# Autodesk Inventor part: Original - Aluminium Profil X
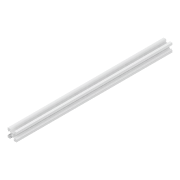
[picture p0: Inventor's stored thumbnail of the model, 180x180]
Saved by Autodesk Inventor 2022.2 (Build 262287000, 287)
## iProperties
Created: 2024-09
Part Number: Original - Aluminium Profil X
Material: Alluminio 6061
Document SubType Name: Modeling
Designer: 18907419
Density: 2.7 g/cm^3
Appearance: Alluminio - Piatto
Author: 18907419
Revision Number: ANY
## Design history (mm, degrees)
feature "Fase1"
node "Solido1"
